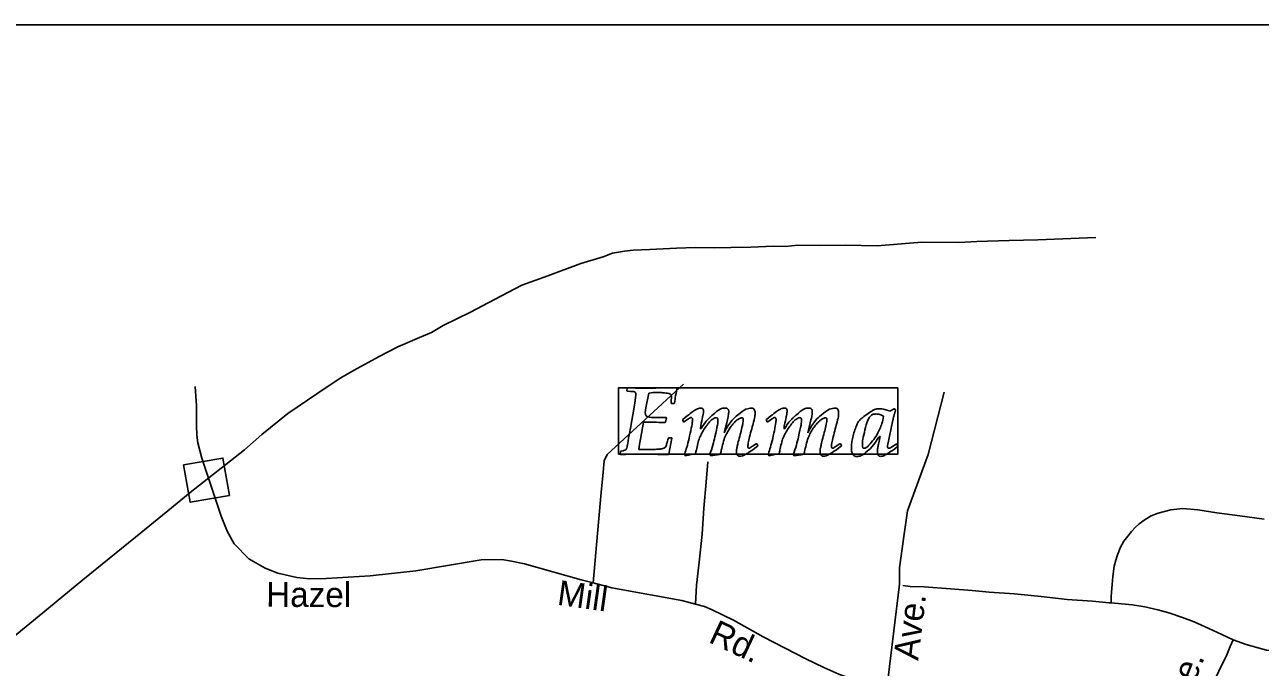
# Model space of a CAD drawing. Extents: x 925297 to 940193, y 663541 to 689899.
# Drawn here: x 927990 to 928734, y 689114 to 689501 of the extents above; entities that cross this region are included whole.
import ezdxf

# ---------------------------------------------------------------- set-up
doc = ezdxf.new("R2010")
doc.units = 0
doc.layers.add('Default', color=7, linetype='Continuous')
doc.layers.add('Sheet Title CELL', color=7, linetype='Continuous')

msp = doc.modelspace()

# ---------------------------------------------------------------- linework, layer by layer
at = {"layer": 'Default'}
for p, q in [((928335.6, 689201.45), (928337.18, 689219.36)), ((928332.38, 689164.79), (928335.6, 689201.45))]:
    msp.add_line(p, q, dxfattribs=at)
for points in [[(928635.28, 689373.06), (928600.27, 689371.66), (928583.07, 689371.22), (928563.49, 689370.56), (928552.72, 689369.98), (928530.28, 689370.17), (928503.52, 689368.08), (928484.3, 689368.46), (928468.48, 689368.25), (928455.68, 689368.51), (928448.05, 689367.61), (928440.9, 689367.76), (928427.3, 689367.24), (928415.29, 689366.95), (928405.7, 689366.88), (928393.7, 689367.12), (928382.46, 689366.56), (928366.5, 689365.83), (928356.45, 689365.5), (928351.12, 689364.82), (928343.88, 689363.66), (928338.32, 689361.4), (928324.85, 689357.47), (928305.08, 689349.99), (928289.28, 689344.27), (928272.9, 689335.67), (928258.31, 689328.09), (928241.93, 689320.01), (928234.89, 689315.69), (928227.68, 689312.68), (928214.7, 689307.17), (928203.3, 689301.36), (928190.09, 689294.01), (928179.93, 689288.17), (928165.89, 689278.74), (928148.33, 689267.01), (928132.72, 689254.2), (928122.29, 689244.96), (928089.49, 689219.36), (928076.08, 689208.34), (928056.47, 689192.45), (928024.71, 689166.57), (928000.69, 689146.84), (927966.92, 689119.16)], [(928332.38, 689164.79), (928325.17, 689166.61), (928290.9, 689176.22), (928283.16, 689177.86), (928277.26, 689178.93), (928264.85, 689178.79), (928225.51, 689172.14), (928198, 689169.05), (928171.4, 689167.5), (928161.39, 689167.28), (928153.7, 689168.12), (928142.3, 689170.71), (928134.7, 689173.75), (928124.76, 689179.37), (928116.02, 689188.44), (928111.8, 689196.02), (928108.16, 689205.02), (928096.44, 689239.96), (928094.14, 689249.18), (928093.51, 689253.94), (928093.22, 689259.62), (928093.29, 689271.61), (928092.55, 689283.3)], [(928337.18, 689219.36), (928338.25, 689231.62), (928338.94, 689238.49), (928340.66, 689242.28), (928386.73, 689284.57)], [(928347.51, 689242.42), (928515.88, 689242.42), (928515.88, 689282.42), (928347.51, 689282.42), (928347.51, 689242.42)], [(928352.81, 689280.43), (928352.61, 689280.65), (928352.84, 689282.21), (928353.1, 689282.44)], [(928382.46, 689282.44), (928382.75, 689282.1)], [(928553.43, 688746.59), (928553.42, 688746.82), (928551.56, 688757.26), (928549.12, 688767.46), (928546.36, 688779.02), (928536.39, 688802.59), (928524.77, 688825.46), (928499.45, 688865.61), (928496.98, 688876.49), (928489.25, 688893.97), (928485.62, 688905.73), (928482.24, 688966.7), (928483.12, 688991.03), (928491.1, 689058.41), (928493.98, 689071.15), (928510.13, 689107.78), (928516.9, 689163.96), (928516.9, 689174), (928519.56, 689192.85), (928521.72, 689208.23), (928534.15, 689242.18), (928543.89, 689279.85)], [(928365.85, 689279.26), (928364.09, 689270.42)], [(928381.3, 689273.14), (928381.04, 689272.91), (928379.57, 689272.91), (928379.34, 689273.14)], [(928354.74, 689258.15), (928356.92, 689270.79)], [(928376.37, 689264.61), (928376.54, 689264.27), (928375.8, 689261.78), (928375.46, 689261.52)], [(928511.11, 689268.27), (928513.72, 689269.8), (928514.65, 689269.12)], [(928362.59, 689261.72), (928360.81, 689251.57)], [(928387.23, 689261.89), (928386.83, 689261.92), (928386.27, 689262.91), (928386.29, 689263.31)], [(928412.77, 689261.29), (928411.21, 689255.2)], [(928437.6, 689261.89), (928437.21, 689261.92), (928436.64, 689262.91), (928436.67, 689263.31)], [(928463.14, 689261.29), (928461.58, 689255.2)], [(928512.92, 689262.94), (928510.83, 689253.36)], [(928377.64, 689252.14), (928377.87, 689252.37), (928379.54, 689252.37), (928379.74, 689252.14), (928377.84, 689242.47), (928377.53, 689242.22)], [(928348.67, 689242.44), (928348.87, 689243.95), (928349.16, 689244.2)], [(928348.87, 689242.25), (928348.67, 689242.44)], [(928371.32, 689242.3), (928358.82, 689242.42)], [(928359.84, 689245.19), (928364.55, 689245.19)], [(928387.94, 689241.34), (928387.37, 689242.16)], [(928403.16, 689241.34), (928402.48, 689242.16)], [(928430.54, 689248.71), (928430.88, 689248.68), (928431.5, 689247.57), (928431.42, 689247.21)], [(928438.31, 689241.34), (928437.75, 689242.16)], [(928453.53, 689241.34), (928452.85, 689242.16)], [(928480.92, 689248.71), (928481.26, 689248.68), (928481.88, 689247.57), (928481.79, 689247.21)], [(928514.91, 689248.45), (928515.25, 689248.45)], [(928515.25, 689248.45), (928515.87, 689247.35), (928515.76, 689246.98)], [(928393.92, 689152), (928394.63, 689163.47), (928396.1, 689177.3), (928397.95, 689194.27), (928399.05, 689209.94), (928400.35, 689225.62), (928401.45, 689237.79)], [(928644.4, 689152.78), (928644.47, 689156.51), (928644.6, 689159.27), (928645.15, 689163.81), (928645.47, 689168.73), (928646.34, 689174.91), (928647.2, 689178.46), (928648.32, 689181.83), (928650, 689186.27), (928652.17, 689189.91), (928654.41, 689192.96), (928656.7, 689195.79), (928658.99, 689198.15), (928661.4, 689200.44), (928664.91, 689203.02), (928668.48, 689205.25), (928672.83, 689206.91), (928680.37, 689208.96), (928687.55, 689209.74), (928696.78, 689208.81), (928708.13, 689207.13), (928722.08, 689205.21), (928736.64, 689203.34)], [(928393.92, 689152), (928385.72, 689154.15), (928343.65, 689161.94), (928332.38, 689164.79)], [(928518.87, 689163.28), (928523.33, 689162.75), (928531.78, 689162.52), (928547.55, 689161.22), (928560.75, 689160.15), (928571.02, 689159.18), (928586.23, 689158.23), (928602.22, 689156.57), (928617.98, 689154.84), (928633.2, 689153.73), (928643.28, 689152.87), (928644.4, 689152.78)], [(928644.4, 689152.78), (928650.77, 689152.26), (928657.37, 689151.52), (928664.75, 689150.36), (928672.49, 689148.62), (928679.15, 689146.68), (928687.51, 689143.99), (928694.42, 689141.31), (928703.24, 689137.4), (928711.1, 689133.71), (928717.98, 689130.56)], [(928508.05, 689100.68), (928504.03, 689101.06), (928480.39, 689109.85), (928471.34, 689113.75), (928460.49, 689118.96), (928434.8, 689132.28), (928416.96, 689142.45), (928403.99, 689148.68), (928399.36, 689150.58), (928393.92, 689152)], [(928717.98, 689130.56), (928725.72, 689127.72), (928738.02, 689124.19), (928751.1, 689123.08), (928758.87, 689123.16), (928768.57, 689124.19), (928778.5, 689125.92), (928787.98, 689129.35), (928798.15, 689133.88), (928810.55, 689140.09), (928816.56, 689142.99)], [(928691.32, 689068.56), (928693.22, 689073.5), (928699.25, 689088.38), (928703.82, 689099.78), (928709.44, 689111.57), (928714.11, 689121.39), (928716.27, 689126.54), (928717.98, 689130.56)]]:
    msp.add_lwpolyline(points, dxfattribs=at)
msp.add_lwpolyline([(928085.53, 689235.9), (928109.21, 689240.06), (928113.16, 689217.6), (928089.48, 689213.44)], close=True, dxfattribs=at)
for points, degree in [([(928356.92, 689270.79), (928357.97, 689277.05), (928357.97, 689278.73), (928357.97, 689279.43), (928357.62, 689279.77), (928357.26, 689280.11), (928356.75, 689280.17), (928356.24, 689280.23), (928352.81, 689280.43)], 3), ([(928353.1, 689282.44), (928357.6, 689282.24), (928365.23, 689282.24), (928366.59, 689282.24), (928382.46, 689282.44)], 3), ([(928379.34, 689273.14), (928379.43, 689276.46), (928379.43, 689277.11), (928379.43, 689277.96), (928379.23, 689278.27), (928379.03, 689278.58), (928378.24, 689278.87), (928377.44, 689279.15), (928375.22, 689279.38), (928372.99, 689279.6), (928371.01, 689279.6), (928367.89, 689279.6), (928365.85, 689279.26)], 3), ([(928382.75, 689282.1), (928382.69, 689281.42), (928381.92, 689277.28), (928381.53, 689275.07), (928381.3, 689273.14)], 3), ([(928364.09, 689270.42), (928363.7, 689268.44), (928363.05, 689264.61), (928369.22, 689264.47), (928370.87, 689264.47), (928373.42, 689264.47), (928376.37, 689264.61)], 3), ([(928386.29, 689263.31), (928388.34, 689265.03), (928391.07, 689267.1), (928393.81, 689269.17), (928395.1, 689269.71), (928396.38, 689270.25), (928397.24, 689270.25), (928397.97, 689270.25), (928398.38, 689269.71), (928398.79, 689269.17), (928398.79, 689268.44), (928398.79, 689267.56), (928398.4, 689265.6), (928398, 689263.65), (928396.07, 689255.2), (928399.79, 689262.12), (928404.43, 689266.18), (928409.08, 689270.25), (928411.97, 689270.25), (928412.85, 689270.25), (928413.42, 689269.61), (928413.99, 689268.97), (928413.99, 689267.95), (928413.99, 689267.13), (928413.73, 689265.63), (928413.48, 689264.13), (928412.77, 689261.29)], 3), ([(928387.37, 689242.16), (928387.4, 689242.27), (928388.05, 689244.34), (928389.44, 689248.79), (928390.79, 689255), (928392.13, 689261.21), (928392.13, 689263.31), (928392.13, 689263.87), (928391.88, 689264.23), (928391.62, 689264.58), (928391.28, 689264.58), (928390.97, 689264.58), (928390.43, 689264.23), (928389.89, 689263.87), (928387.23, 689261.89)], 3), ([(928402.48, 689242.16), (928404.09, 689246.24), (928405.78, 689253.48), (928407.47, 689260.73), (928407.47, 689263.22), (928407.47, 689263.82), (928407.2, 689264.13), (928406.93, 689264.44), (928406.53, 689264.44), (928405.8, 689264.44), (928404.39, 689263.53), (928402.99, 689262.63), (928400.96, 689259.96), (928398.94, 689257.3), (928397.48, 689254.48), (928396.02, 689251.66), (928395.12, 689247.82), (928394.23, 689243.97), (928394.15, 689242.44), (928392.3, 689242.44), (928387.94, 689241.34)], 3), ([(928411.21, 689255.2), (928414.81, 689262.37), (928419.74, 689266.24), (928424.67, 689270.11), (928427.82, 689270.11), (928428.84, 689270.11), (928429.35, 689269.31), (928429.86, 689268.52), (928429.86, 689267.33), (928429.86, 689265.32), (928428.81, 689261.32), (928425.55, 689249.16), (928425.55, 689247.06), (928425.55, 689246.1), (928426.2, 689246.1), (928426.97, 689246.1), (928430.54, 689248.71)], 3), ([(928436.67, 689263.31), (928438.71, 689265.03), (928441.45, 689267.1), (928444.18, 689269.17), (928445.47, 689269.71), (928446.76, 689270.25), (928447.61, 689270.25), (928448.35, 689270.25), (928448.76, 689269.71), (928449.17, 689269.17), (928449.17, 689268.44), (928449.17, 689267.56), (928448.77, 689265.6), (928448.38, 689263.65), (928446.45, 689255.2), (928450.16, 689262.12), (928454.81, 689266.18), (928459.46, 689270.25), (928462.35, 689270.25), (928463.23, 689270.25), (928463.79, 689269.61), (928464.36, 689268.97), (928464.36, 689267.95), (928464.36, 689267.13), (928464.11, 689265.63), (928463.85, 689264.13), (928463.14, 689261.29)], 3), ([(928437.75, 689242.16), (928437.77, 689242.27), (928438.43, 689244.34), (928439.82, 689248.79), (928441.16, 689255), (928442.51, 689261.21), (928442.51, 689263.31), (928442.51, 689263.87), (928442.25, 689264.23), (928442, 689264.58), (928441.66, 689264.58), (928441.35, 689264.58), (928440.81, 689264.23), (928440.27, 689263.87), (928437.6, 689261.89)], 3), ([(928452.85, 689242.16), (928454.47, 689246.24), (928456.16, 689253.48), (928457.84, 689260.73), (928457.84, 689263.22), (928457.84, 689263.82), (928457.57, 689264.13), (928457.3, 689264.44), (928456.91, 689264.44), (928456.17, 689264.44), (928454.77, 689263.53), (928453.36, 689262.63), (928451.34, 689259.96), (928449.31, 689257.3), (928447.85, 689254.48), (928446.39, 689251.66), (928445.5, 689247.82), (928444.61, 689243.97), (928444.52, 689242.44), (928442.68, 689242.44), (928438.31, 689241.34)], 3), ([(928461.58, 689255.2), (928465.18, 689262.37), (928470.12, 689266.24), (928475.05, 689270.11), (928478.19, 689270.11), (928479.21, 689270.11), (928479.72, 689269.31), (928480.23, 689268.52), (928480.23, 689267.33), (928480.23, 689265.32), (928479.19, 689261.32), (928475.93, 689249.16), (928475.93, 689247.06), (928475.93, 689246.1), (928476.58, 689246.1), (928477.34, 689246.1), (928480.92, 689248.71)], 3), ([(928515.76, 689246.98), (928510.63, 689243.21), (928508.71, 689242.16), (928506.8, 689241.11), (928505.52, 689241.11), (928504.62, 689241.11), (928504.09, 689241.88), (928503.57, 689242.64), (928503.57, 689243.8), (928503.57, 689245), (928504.02, 689247.26), (928504.48, 689249.53), (928505.98, 689255.51), (928501.22, 689247.35), (928497.42, 689244.22), (928493.62, 689241.08), (928491.21, 689241.08), (928489.91, 689241.08), (928488.96, 689242.25), (928488.01, 689243.41), (928488.01, 689246.44), (928488.01, 689249.11), (928488.8, 689252.65), (928489.59, 689256.19), (928491.04, 689259.82), (928491.78, 689261.63), (928492.78, 689262.75), (928493.79, 689263.87), (928497.13, 689266.31), (928500.48, 689268.75), (928501.88, 689269.26), (928503.29, 689269.77), (928505.04, 689269.77), (928506.29, 689269.77), (928507.99, 689269.39), (928509.69, 689269), (928511.11, 689268.27)], 3), ([(928507.28, 689265.37), (928504.76, 689266.65), (928502.63, 689266.65), (928500.42, 689266.65), (928499.06, 689264.89), (928497.7, 689263.14), (928496.11, 689257.07), (928494.53, 689251), (928494.53, 689248.09), (928494.53, 689245.96), (928495.66, 689245.96), (928496.85, 689245.96), (928499.91, 689249.53), (928502.97, 689253.1), (928504.94, 689257.44), (928506.91, 689261.78), (928507.28, 689265.37)], 3), ([(928514.65, 689269.12), (928513.94, 689267.44), (928512.92, 689262.94)], 2), ([(928349.16, 689244.2), (928351.37, 689244.74), (928351.82, 689245.02), (928352.05, 689245.17), (928352.22, 689245.42), (928352.39, 689245.68), (928352.69, 689246.88), (928352.98, 689248.09), (928354.74, 689258.15)], 3), ([(928375.46, 689261.52), (928370.19, 689261.63), (928364.92, 689261.78), (928363.92, 689261.78), (928362.59, 689261.72)], 3), ([(928431.42, 689247.21), (928426.69, 689243.75), (928424.45, 689242.47), (928422.21, 689241.2), (928420.79, 689241.2), (928419.83, 689241.2), (928419.24, 689241.93), (928418.66, 689242.67), (928418.66, 689243.72), (928418.66, 689245), (928419.16, 689247.26), (928419.66, 689249.53), (928420.93, 689254.41), (928422.09, 689258.91), (928422.42, 689260.54), (928422.75, 689262.17), (928422.75, 689263.02), (928422.75, 689264.35), (928421.84, 689264.35), (928421.16, 689264.35), (928419.83, 689263.53), (928418.49, 689262.71), (928416.51, 689260.49), (928414.53, 689258.26), (928412.98, 689255.36), (928411.44, 689252.45), (928410.3, 689247.99), (928409.17, 689243.52), (928409.17, 689242.16), (928407.13, 689242.16), (928403.16, 689241.34)], 3), ([(928481.79, 689247.21), (928477.06, 689243.75), (928474.82, 689242.47), (928472.58, 689241.2), (928471.16, 689241.2), (928470.2, 689241.2), (928469.62, 689241.93), (928469.04, 689242.67), (928469.04, 689243.72), (928469.04, 689245), (928469.53, 689247.26), (928470.03, 689249.53), (928471.31, 689254.41), (928472.47, 689258.91), (928472.79, 689260.54), (928473.12, 689262.17), (928473.12, 689263.02), (928473.12, 689264.35), (928472.21, 689264.35), (928471.53, 689264.35), (928470.2, 689263.53), (928468.87, 689262.71), (928466.88, 689260.49), (928464.9, 689258.26), (928463.36, 689255.36), (928461.81, 689252.45), (928460.68, 689247.99), (928459.54, 689243.52), (928459.54, 689242.16), (928457.5, 689242.16), (928453.53, 689241.34)], 3), ([(928360.81, 689251.57), (928360.01, 689247.18), (928359.84, 689245.19)], 2), ([(928364.55, 689245.19), (928368.12, 689245.19), (928370.77, 689245.36), (928373.42, 689245.53), (928374.38, 689245.82), (928375.35, 689246.1), (928375.8, 689246.67), (928376.25, 689247.23), (928376.91, 689249.7), (928377.05, 689250.32), (928377.64, 689252.14)], 3), ([(928510.83, 689253.36), (928509.72, 689248.25), (928509.72, 689247.12), (928509.72, 689246.02), (928510.46, 689246.02), (928511.36, 689246.02), (928514.91, 689248.45)], 3), ([(928358.82, 689242.42), (928354.51, 689242.42), (928348.87, 689242.25)], 2), ([(928377.53, 689242.22), (928372.99, 689242.3), (928371.32, 689242.3)], 2)]:
    msp.add_open_spline(points, degree=degree, dxfattribs=at)
at = {"layer": 'Sheet Title CELL'}
msp.add_lwpolyline([(927148.43, 689501.34), (930192.06, 689501.34), (930192.06, 687400.3), (927148.43, 687400.3)], close=True, dxfattribs=at)

# ---------------------------------------------------------------- texts
at = {"layer": 'Default'}
for s, rotation, p in [('Hazel', 359.80385, (928135.21, 689150.41)), ('Mill', 352.02751, (928310.13, 689151.71)), ('Ave.', 83.13137, (928528.17, 689117.71)), ('Rd.', 334.91662, (928401.14, 689129.36)), ('Ave.', 68.36504, (928686.26, 689082.79))]:
    msp.add_text(s, height=15, rotation=rotation, dxfattribs=at).set_placement(p)

doc.saveas('drawing.dxf')
